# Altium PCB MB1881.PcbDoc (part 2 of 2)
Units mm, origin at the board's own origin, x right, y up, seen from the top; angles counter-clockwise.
Board outline 150 x 109 mm, 4 copper layers (Top Layer, Layer 1, Layer 2, Bottom Layer), stack 1.782 mm thick; 66 components, 175 nets, 880 pads, 302 vias.
Unrouted connection lines stored in the file: 35.
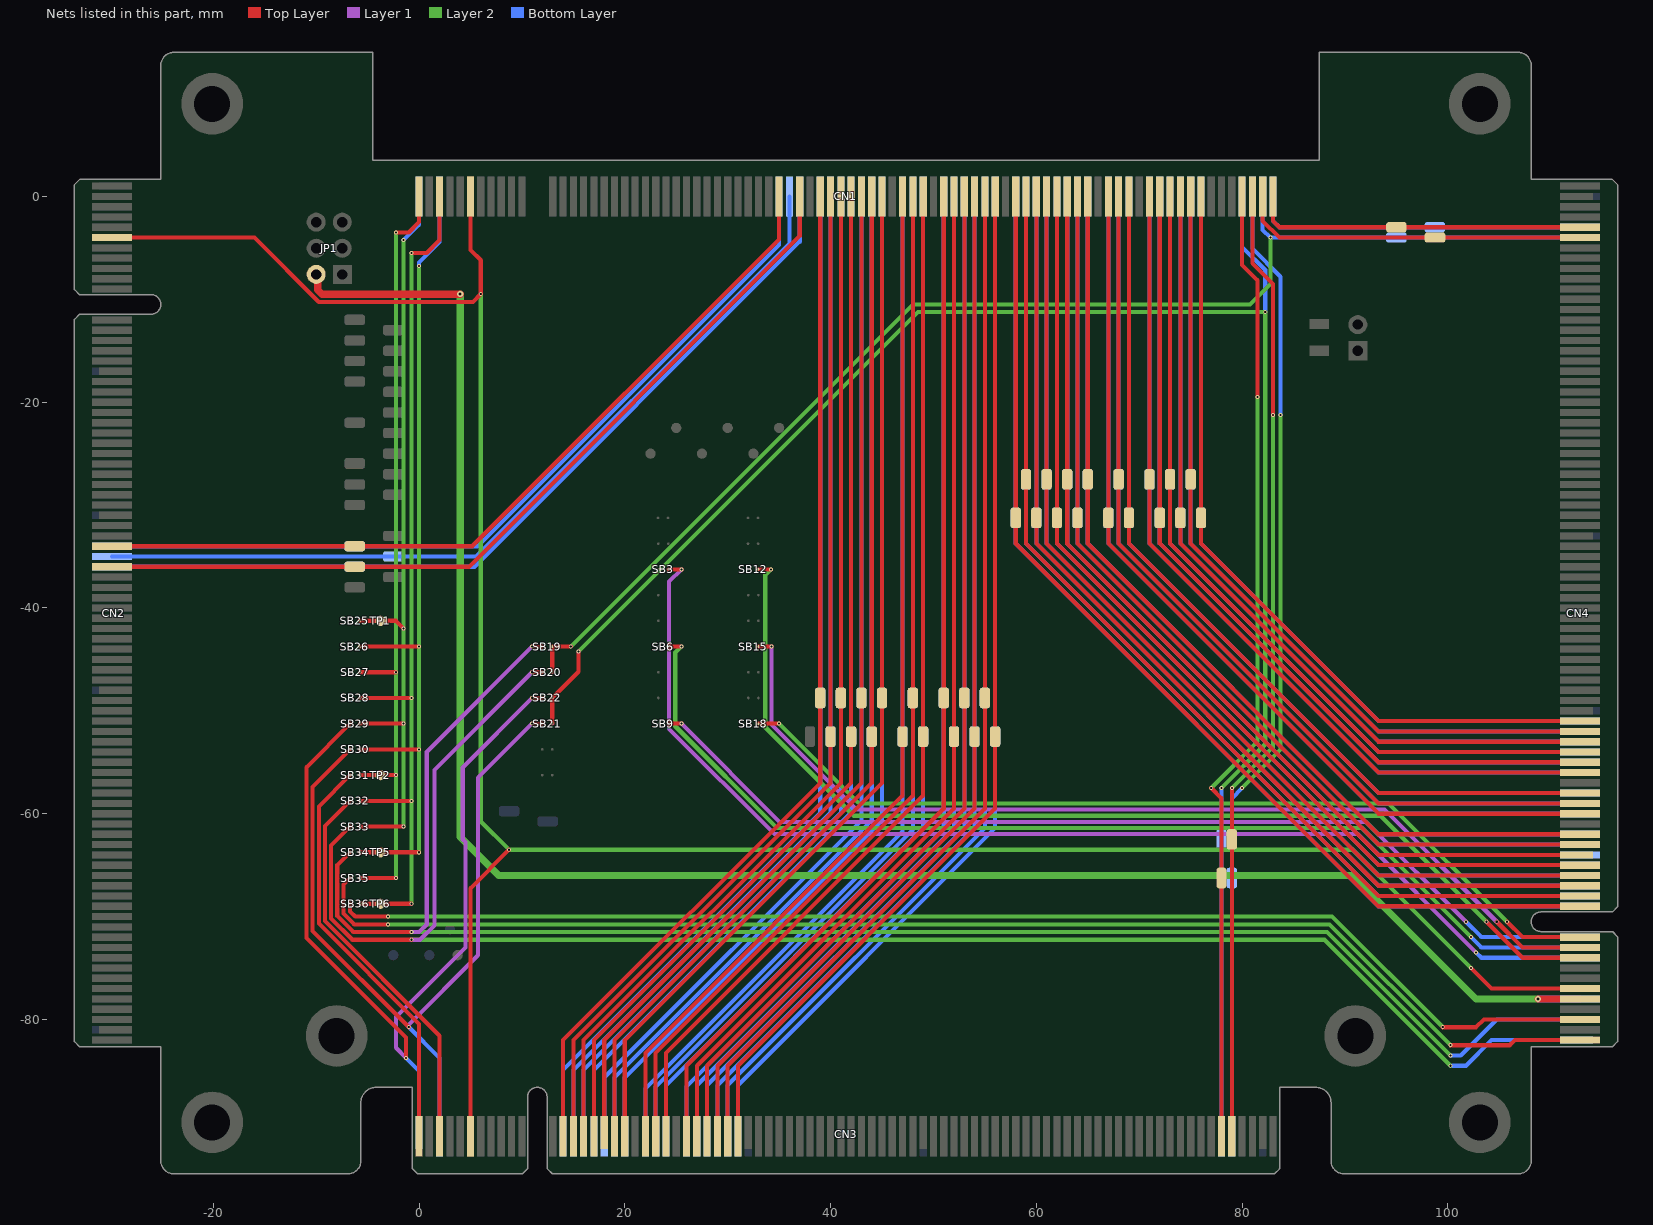
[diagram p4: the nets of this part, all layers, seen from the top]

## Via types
v1: diameter 0.6, hole 0.3, Top Layer to Bottom Layer, 181 vias
v2: diameter 0.381, hole 0.203, Top Layer to Bottom Layer, 121 vias

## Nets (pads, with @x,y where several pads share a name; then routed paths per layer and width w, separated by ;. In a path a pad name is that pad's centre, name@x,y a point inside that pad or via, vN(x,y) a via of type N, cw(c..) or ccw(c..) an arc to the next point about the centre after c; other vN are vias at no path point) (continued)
M2_D_BRAKE: CN1.A55 CN3.A30 pad.TP@56,-52.5 | length 101.7
  Bottom Layer w0.4: CN3.A30@31,-91.35 31,-86.395 56,-61.395 pad.TP@56,-52.5 CN1.A55@56,0
M2_Enable_A: CN1.A80 CN3.A78 pad.TP@79,-66.25 | length 94.5
  Layer 2 w0.4: v2(80,-57.5) 83.75,-53.75 v2(83.75,-21.25)
  Bottom Layer w0.4: CN3.A78@79,-91.35 79,-58.5 v2(80,-57.5) ; CN1.A80@81,0 81,-5.058 83.75,-7.808 v2(83.75,-21.25)
M2_Enable_B1: CN1.B79 CN3.B77 pad.TP@78,-66.25 | length 94.2
  Top Layer w0.4: v2(77,-57.5) 78,-58.5 CN3.B77@78,-91.35 ; CN1.B79@80,0 80,-6.654 81.5,-8.154 v2(81.5,-19.5)
  Layer 2 w0.4: v2(77,-57.5) 81.5,-53 v2(81.5,-19.5)
M2_Enable_B2: CN1.B80 CN3.B78 pad.TP@79,-62.5 | length 93.8
  Top Layer w0.4: CN3.B78@79,-91.35 v2(79,-57.5) ; CN1.B80@81,0 81,-6.5 83,-8.5 v2(83,-21.25)
  Layer 2 w0.4: v2(79,-57.5) 83,-53.5 v2(83,-21.25)
M2_Encoder_A: CN1.B41 CN3.B16 pad.TP@42,-52.5 | length 101.7
  Top Layer w0.4: CN3.B16@17,-91.35 17,-82 42,-57 CN1.B41@42,0
M2_Encoder_B: CN1.B42 CN3.B17 pad.TP@43,-48.75 | length 101.4
  Top Layer w0.4: CN3.B17@18,-90.995 18,-82 43,-57 CN1.B42@43,0
M2_Encoder_Z: CN1.B43 CN3.B18 pad.TP@44,-52.5 | length 101.7
  Top Layer w0.4: CN3.B18@19,-91.35 19,-82 44,-57 CN1.B43@44,0
M2_Hall_H1: CN1.A43 CN3.A18 pad.TP@44,-52.5 | length 101.7
  Bottom Layer w0.4: CN3.A18@19,-91.35 19,-85.65 44,-60.65 CN1.A43@44,0
M2_Hall_H2: CN1.A44 CN3.A19 pad.TP@45,-48.75 | length 101.7
  Bottom Layer w0.4: CN3.A19@20,-91.35 20,-85.65 45,-60.65 CN1.A44@45,0
M2_Hall_H3: CN1.B44 CN3.B19 pad.TP@45,-48.75 | length 101.7
  Top Layer w0.4: CN3.B19@20,-91.35 20,-82 45,-57 CN1.B44@45,0
M2_Master_EN: CN1.A41 CN3.A16 pad.TP@42,-52.5 | length 101.7
  Bottom Layer w0.4: CN3.A16@17,-91.35 17,-84.9 42,-59.9 CN1.A41@42,0
M2_PWM_UH: CN1.A38 CN3.A13 pad.TP@39,-48.75 | length 101.7
  Bottom Layer w0.4: CN3.A13@14,-91.35 14,-84.9 39,-59.9 CN1.A38@39,0
M2_PWM_UL: CN1.B38 CN3.B13 pad.TP@39,-48.75 | length 101.7
  Top Layer w0.4: CN3.B13@14,-91.35 14,-82 39,-57 CN1.B38@39,0
M2_PWM_VH: CN1.A39 CN3.A14 pad.TP@40,-52.5 | length 101.7
  Bottom Layer w0.4: CN3.A14@15,-91.35 15,-84.9 40,-59.9 CN1.A39@40,0
M2_PWM_VL: CN1.B39 CN3.B14 pad.TP@40,-52.5 | length 101.7
  Top Layer w0.4: CN3.B14@15,-91.35 15,-82 40,-57 CN1.B39@40,0
M2_PWM_WH: CN1.A40 CN3.A15 pad.TP@41,-48.75 | length 101.7
  Bottom Layer w0.4: CN3.A15@16,-91.35 16,-84.9 41,-59.9 CN1.A40@41,0
M2_PWM_WL: CN1.B40 CN3.B15 pad.TP@41,-48.75 | length 101.7
  Top Layer w0.4: CN3.B15@16,-91.35 16,-82 41,-57 CN1.B40@41,0
M2_Res.Ex: CN1.B53 CN3.B28 pad.TP@54,-52.5 | length 101.7
  Top Layer w0.4: CN3.B28@29,-91.35 29,-84.5 54,-59.5 CN1.B53@54,0
M2_Resolv_Cos: CN1.B55 CN3.B30 pad.TP@56,-52.5 | length 101.7
  Top Layer w0.4: CN3.B30@31,-91.35 31,-84.5 56,-59.5 CN1.B55@56,0
M2_Resolv_Sin: CN1.B54 CN3.B29 pad.TP@55,-48.75 | length 101.7
  Top Layer w0.4: CN3.B29@30,-91.35 30,-84.5 55,-59.5 CN1.B54@55,0
M2_SHUNT1+: CN1.A46 CN3.A21 pad.TP@47,-52.5 | length 101.7
  Bottom Layer w0.4: CN3.A21@22,-91.35 22,-86.708 47,-61.708 CN1.A46@47,0
M2_SHUNT1-: CN1.B46 CN3.B21 pad.TP@47,-52.5 | length 101.7
  Top Layer w0.4: CN3.B21@22,-91.35 22,-83.25 47,-58.25 CN1.B46@47,0
M2_SHUNT2+: CN1.A47 CN3.A22 pad.TP@48,-48.75 | length 101.7
  Bottom Layer w0.4: CN3.A22@23,-91.35 23,-86.554 48,-61.554 CN1.A47@48,0
M2_SHUNT2-: CN1.B47 CN3.B22 pad.TP@48,-48.75 | length 101.7
  Top Layer w0.4: CN3.B22@23,-91.35 23,-83.25 48,-58.25 CN1.B47@48,0
M2_SHUNT3+: CN1.A48 CN3.A23 pad.TP@49,-52.5 | length 101.7
  Bottom Layer w0.4: CN3.A23@24,-91.35 24,-86.4 49,-61.4 CN1.A48@49,0
M2_SHUNT3-: CN1.B48 CN3.B23 pad.TP@49,-52.5 | length 101.7
  Top Layer w0.4: CN3.B23@24,-91.35 24,-83.25 49,-58.25 CN1.B48@49,0
M2_SPI1_MISO: CN3.B01 SB31.2 | length 40.4
  Top Layer w0.4: SB31.2@-6.7,-56.25 -9.741,-59.291 -9.741,-70.687 0,-80.427 CN3.B01@0,-91.35
M2_SPI1_nSS: CN3.A01 SB22.2 SB29.2 | length 88.1
  Top Layer w0.4: SB29.2@-6.7,-51.25 -10.937,-55.487 -10.937,-72.063 -1.25,-81.75 v2(-1.25,-83.75) ; v2@11,-48.75 SB22.2@11.975,-48.75
  Layer 1 w0.4: v2(-1.25,-83.75) -2.25,-82.75 -2.25,-79.75 4.5,-73 4.5,-62.75 4.25,-62.5 4.25,-55.5 v2(11,-48.75)
  Bottom Layer w0.4: v2(-1.25,-83.75) 0,-85 CN3.A01@0,-90.995
M2_SPI2_MISO: CN3.B03 SB32.2 | length 38.2
  Top Layer w0.4: SB32.2@-6.7,-58.75 -9.142,-61.193 -9.142,-70.439 2,-81.582 CN3.B03@2,-91.35
M2_SPI2_nSS: CN3.A03 SB21.2 SB30.2 | length 79.4
  Top Layer w0.4: SB30.2@-6.7,-53.75 -10.339,-57.389 -10.339,-71.411 v2(-1,-80.75) ; v2@11,-51.25 SB21.2@11.975,-51.25
  Layer 1 w0.4: -0.991,-80.5 5.75,-73.759 5.75,-56.5 v2(11,-51.25)
  Bottom Layer w0.4: v2(-1,-80.75) 2,-83.75 CN3.A03@2,-91.35
M2_SPI_nSS: CN1.A79 CN3.A77 pad.TP@78,-62.5 SB21.1 SB22.1 | length 183.7
  Top Layer w0.4: SB21.1@12.95,-51.25 SB22.1@12.95,-48.75 15.5,-46.2 v2(15.5,-44.25)
  Layer 2 w0.4: v2(15.5,-44.25) 48.5,-11.25 v2(82.25,-11.25) 82.25,-53.25 v2(78,-57.5)
  Bottom Layer w0.18: CN3.A77@78,-92.5 CN3.A77@78,-91.35
  Bottom Layer w0.4: CN3.A77@78,-91.35 v2(78,-57.5) ; CN1.A79@80,0 80,-4.904 82.25,-7.154 v2(82.25,-11.25)
M2_TEMP_ID: CN1.A53 CN3.A28 pad.TP@54,-52.5 | length 101.7
  Bottom Layer w0.4: CN3.A28@29,-91.35 29,-86.395 54,-61.395 pad.TP@54,-52.5 CN1.A53@54,0
M2_Timer_ETR: CN1.A42 CN3.A17 pad.TP@43,-48.75 | length 101.7
  Bottom Layer w0.4: CN3.A17@18,-91.35 18,-85.65 43,-60.65 CN1.A42@43,0
M2_VBUS: CN1.A54 CN3.A29 pad.TP@55,-48.75 | length 101.7
  Bottom Layer w0.4: CN3.A29@30,-91.35 30,-86.395 55,-61.395 pad.TP@55,-48.75 CN1.A54@55,0
M2_VOL+_U: CN1.A50 CN3.A25 pad.TP@51,-48.75 | length 101.7
  Bottom Layer w0.4: CN3.A25@26,-91.35 26,-86.5 51,-61.5 pad.TP@51,-48.75 CN1.A50@51,0
M2_VOL+_V: CN1.A51 CN3.A26 pad.TP@52,-52.5 | length 101.7
  Bottom Layer w0.4: CN3.A26@27,-91.35 27,-86.395 52,-61.395 pad.TP@52,-52.5 CN1.A51@52,0
M2_VOL+_W: CN1.A52 CN3.A27 pad.TP@53,-48.75 | length 101.7
  Bottom Layer w0.4: CN3.A27@28,-91.35 28,-86.395 53,-61.395 pad.TP@53,-48.75 CN1.A52@53,0
M2_VOL-_U: CN1.B50 CN3.B25 pad.TP@51,-48.75 | length 101.7
  Top Layer w0.4: CN3.B25@26,-91.35 26,-84.5 51,-59.5 CN1.B50@51,0
M2_VOL-_V: CN1.B51 CN3.B26 pad.TP@52,-52.5 | length 101.7
  Top Layer w0.4: CN3.B26@27,-91.35 27,-84.5 52,-59.5 CN1.B51@52,0
M2_VOL-_W: CN1.B52 CN3.B27 pad.TP@53,-48.75 | length 101.7
  Top Layer w0.4: CN3.B27@28,-91.35 28,-84.5 53,-59.5 CN1.B52@53,0
M3_5V: CN4.A05 CN4.B05 JP1.2 | length 187.3
  Top Layer w0.7: JP1.2@-9.85,-8.08 -9.85,-9.09 -9.44,-9.5 v1(4,-9.5) ; v1(108.75,-78) CN4.B05@112.855,-78
  Layer 2 w0.7: v1(4,-9.5) 4,-62.27 7.74,-66.01 7.75,-66 90.73,-66 102.73,-78 v1(108.75,-78)
  Bottom Layer w0.7: v1(108.75,-78) CN4.A05@112.855,-78
M3_ADC_1: CN4.A09 SB3.1 | length 115
  Top Layer w0.4: SB3.1@24.238,-36.25 v2(25.5,-36.25)
  Layer 1 w0.4: v2(25.5,-36.25) 24.304,-37.446 24.304,-51.745 34.549,-61.991 91.241,-61.991 v2(102.75,-73.5)
  Bottom Layer w0.4: v2(102.75,-73.5) 103.25,-74 104,-74 CN4.A09@112.855,-74
M3_ADC_2: CN4.A10 SB6.1 | length 106.1
  Top Layer w0.4: SB6.1@24.238,-43.75 v2(25.5,-43.75)
  Layer 2 w0.4: v2(25.5,-43.75) 24.902,-44.348 24.902,-51.498 34.797,-61.392 91.642,-61.392 v2(102.25,-72)
  Bottom Layer w0.4: v2(102.25,-72) 103.25,-73 CN4.A10@112.855,-73
M3_ADC_3: CN4.A11 SB9.1 | length 97.2
  Top Layer w0.4: SB9.1@24.238,-51.25 v2(25.5,-51.25)
  Layer 1 w0.4: v2(25.5,-51.25) 35.044,-60.794 92.044,-60.794 v2(101.75,-70.5)
  Bottom Layer w0.4: v2(101.75,-70.5) 103.25,-72 CN4.A11@112.855,-72
M3_ADC_4: CN4.B09 SB12.1 | length 105.3
  Top Layer w0.4: SB12.1@32.95,-36.25 v2(34.213,-36.25) ; v2(103.75,-70.5) 107.25,-74 CN4.B09@112.855,-74
  Layer 2 w0.4: v2(34.213,-36.25) 33.652,-36.811 33.652,-51.594 42.255,-60.196 93.446,-60.196 v2(103.75,-70.5)
M3_ADC_5: CN4.B10 SB15.1 | length 96.4
  Top Layer w0.4: SB15.1@32.988,-43.75 v2@34.25,-43.75 ; v2(104.75,-70.5) 107.25,-73 CN4.B10@112.855,-73
  Layer 1 w0.4: v2(34.25,-43.75) 34.25,-51.346 42.502,-59.598 93.848,-59.598 v2(104.75,-70.5)
M3_ADC_6: CN4.B11 SB18.1 | length 88.5
  Top Layer w0.4: SB18.1@32.988,-51.25 v2(35,-51.25) ; v2(105.75,-70.5) 107.25,-72 CN4.B11@112.855,-72
  Layer 2 w0.4: v2(35,-51.25) 42.75,-59 94.25,-59 v2(105.75,-70.5)
M3_BKIN: CN1.A57 CN4.A12 pad.TP@58,-31.25 | length 103.2
  Bottom Layer w0.4: CN1.A57@58,0 pad.TP@58,-31.25 58,-33.75 93.25,-69 CN4.A12@112.855,-69
M3_BKIN2: CN1.B57 CN4.B12 pad.TP@58,-31.25 | length 103.5
  Top Layer w0.4: CN1.B57@58,0 pad.TP@58,-31.25 58,-33.75 93.25,-69 CN4.B12@113.1,-69
M3_D_BRAKE: CN1.A75 CN4.A30 pad.TP@76,-31.25 | length 77.8
  Bottom Layer w0.4: CN1.A75@76,0 pad.TP@76,-31.25 76,-33.75 93.25,-51 CN4.A30@112.855,-51
M3_Enable_A: CN1.A82 CN4.A78 pad.TP@98.74,-3 | length 33.5
  Bottom Layer w0.4: CN1.A82@83,0 83,-2.37 83.63,-3 CN4.A78@113.85,-3
M3_Enable_B1: CN1.B81 CN4.B77 pad.TP@98.75,-4 | length 33.9
  Top Layer w0.4: CN1.B81@82,0 82,-2.37 83.63,-4 CN4.B77@112.855,-4
M3_Enable_B2: CN1.B82 CN4.B78 pad.TP@95,-3 | length 32.5
  Top Layer w0.4: CN1.B82@83,0 83,-2.37 83.63,-3 CN4.B78@112.855,-3
M3_Encoder_A: CN1.B61 CN4.B16 pad.TP@62,-31.25 | length 97.8
  Top Layer w0.4: CN1.B61@62,0 pad.TP@62,-31.25 62,-33.75 93.25,-65 CN4.B16@113.1,-65
M3_Encoder_B: CN1.B62 CN4.B17 pad.TP@63,-27.5 | length 95.8
  Top Layer w0.4: CN1.B62@63,0 pad.TP@63,-27.5 63,-33.75 93.25,-64 CN4.B17@112.5,-64
M3_Encoder_Z: CN1.B63 CN4.B18 pad.TP@64,-31.25 | length 94.7
  Top Layer w0.4: CN1.B63@64,0 pad.TP@64,-31.25 64,-33.75 93.25,-63 CN4.B18@112.855,-63
M3_Hall_H1: CN1.A63 CN4.A18 pad.TP@64,-31.25 | length 94.7
  Bottom Layer w0.4: CN1.A63@64,0 64,-25 64,-33.75 93.25,-63 CN4.A18@112.855,-63
M3_Hall_H2: CN1.A64 CN4.A19 pad.TP@65,-27.5 | length 93.3
  Bottom Layer w0.4: CN1.A64@65,0 65,-25 65,-33.75 93.25,-62 CN4.A19@112.855,-62
M3_Hall_H3: CN1.B64 CN4.B19 pad.TP@65,-27.5 | length 93.3
  Top Layer w0.4: CN1.B64@65,0 pad.TP@65,-27.5 65,-33.75 93.25,-62 CN4.B19@112.855,-62
M3_Master_EN: CN1.A61 CN4.A16 pad.TP@62,-31.25 | length 97.5
  Bottom Layer w0.4: CN1.A61@62,0 62,-25 pad.TP@62,-31.25 62,-33.75 93.25,-65 CN4.A16@112.855,-65
M3_PWM_UH: CN1.A58 CN4.A13 pad.TP@59,-27.5 | length 101.8
  Bottom Layer w0.4: CN1.A58@59,0 59,-25 59,-28.75 59,-33.75 93.25,-68 CN4.A13@112.855,-68
M3_PWM_UL: CN1.B58 CN4.B13 pad.TP@59,-27.5 | length 102
  Top Layer w0.4: CN1.B58@59,0 pad.TP@59,-27.5 59,-33.75 93.25,-68 CN4.B13@113.1,-68
M3_PWM_VH: CN1.A59 CN4.A14 pad.TP@60,-31.25 | length 100.4
  Bottom Layer w0.4: CN1.A59@60,0 60,-25.25 pad.TP@60,-31.25 60,-33.75 93.25,-67 CN4.A14@112.855,-67
M3_PWM_VL: CN1.B59 CN4.B14 pad.TP@60,-31.25 | length 100.6
  Top Layer w0.4: CN1.B59@60,0 pad.TP@60,-31.25 60,-33.75 93.25,-67 CN4.B14@113.1,-67
M3_PWM_WH: CN1.A60 CN4.A15 pad.TP@61,-27.5 | length 99
  Bottom Layer w0.4: CN1.A60@61,0 61,-25.25 61,-28.75 61,-33.75 93.25,-66 CN4.A15@112.855,-66
M3_PWM_WL: CN1.B60 CN4.B15 pad.TP@61,-27.5 | length 99.2
  Top Layer w0.4: CN1.B60@61,0 pad.TP@61,-27.5 61,-33.75 93.25,-66 CN4.B15@113.1,-66
M3_Res.Ex: CN1.B73 CN4.B28 pad.TP@74,-31.25 | length 80.8
  Top Layer w0.4: CN1.B73@74,0 pad.TP@74,-31.25 74,-33.75 93.25,-53 CN4.B28@113.1,-53
M3_Resolv_Cos: CN1.B75 CN4.B30 pad.TP@76,-31.25 | length 78
  Top Layer w0.4: CN1.B75@76,0 pad.TP@76,-31.25 76,-33.75 93.25,-51 CN4.B30@113.1,-51
M3_Resolv_Sin: CN1.B74 CN4.B29 pad.TP@75,-27.5 | length 79.4
  Top Layer w0.4: CN1.B74@75,0 pad.TP@75,-27.5 75,-33.75 93.25,-52 CN4.B29@113.1,-52
M3_SHUNT1+: CN1.A66 CN4.A21 pad.TP@67,-31.25 | length 90.5
  Bottom Layer w0.4: CN1.A66@67,0 67,-25 67,-33.75 93.25,-60 CN4.A21@112.855,-60
M3_SHUNT1-: CN1.B66 CN4.B21 pad.TP@67,-31.25 | length 90.5
  Top Layer w0.4: CN1.B66@67,0 pad.TP@67,-31.25 67,-33.75 93.25,-60 CN4.B21@112.855,-60
M3_SHUNT2+: CN1.A67 CN4.A22 pad.TP@68,-27.5 | length 89.1
  Bottom Layer w0.4: CN1.A67@68,0 68,-25 68,-28.75 68,-33.75 93.25,-59 CN4.A22@112.855,-59
M3_SHUNT2-: CN1.B67 CN4.B22 pad.TP@68,-27.5 | length 89.3
  Top Layer w0.4: CN1.B67@68,0 pad.TP@68,-27.5 68,-33.75 93.25,-59 CN4.B22@113.1,-59
M3_SHUNT3+: CN1.A68 CN4.A23 pad.TP@69,-31.25 | length 87.6
  Bottom Layer w0.4: CN1.A68@69,0 69,-25 69,-33.75 93.25,-58 CN4.A23@112.855,-58
M3_SHUNT3-: CN1.B68 CN4.B23 pad.TP@69,-31.25 | length 87.9
  Top Layer w0.4: CN1.B68@69,0 pad.TP@69,-31.25 69,-33.75 93.25,-58 CN4.B23@113.1,-58
M3_SPI1_MISO: CN4.B01 SB35.2 | length 129.4
  Top Layer w0.4: SB35.2@-6.7,-66.25 -7.348,-66.898 -7.348,-69.696 -6.294,-70.75 v2(-3,-70.75) ; v2(100.25,-82.5) 106.014,-82.5 106.514,-82 CN4.B01@112.855,-82
  Layer 2 w0.4: v2(-3,-70.75) 88.5,-70.75 v2(100.25,-82.5)
M3_SPI1_nSS: CN4.A01 SB20.2 SB33.2 | length 170
  Top Layer w0.4: SB33.2@-6.7,-61.25 -8.544,-63.094 -8.544,-70.191 -6.486,-72.25 v2(-0.75,-72.25) ; v2@11,-46.25 SB20.2@11.975,-46.25
  Layer 1 w0.4: v2(-0.75,-72.25) 0.096,-72.25 1.5,-70.846 1.5,-55.75 v2(11,-46.25)
  Layer 2 w0.4: v2(-0.75,-72.25) 88,-72.25 v2(100.25,-84.5)
  Bottom Layer w0.4: v2(100.25,-84.5) 101.75,-84.5 104.25,-82 CN4.A01@112.5,-82
M3_SPI2_MISO: CN4.B03 SB36.2 | length 125.3
  Top Layer w0.4: SB36.2@-6.7,-68.75 -6.7,-69.498 -6.198,-70 v2(-3,-70) ; v2(99.5,-80.75) 102.75,-80.75 103.5,-80 CN4.B03@112.855,-80
  Layer 2 w0.4: v2(-3,-70) 88.75,-70 v2(99.5,-80.75)
M3_SPI2_nSS: CN4.A03 SB19.2 SB34.2 | length 168.6
  Top Layer w0.4: SB34.2@-6.7,-63.75 -7.946,-64.996 -7.946,-69.944 -6.39,-71.5 v2(-0.75,-71.5) ; v2@11,-43.75 SB19.2@11.975,-43.75
  Layer 1 w0.4: v2(-0.75,-71.5) 0,-71.5 0.75,-70.75 0.75,-54 v2(11,-43.75)
  Layer 2 w0.4: v2(-0.75,-71.5) 88.25,-71.5 v2(100.25,-83.5)
  Bottom Layer w0.4: v2(100.25,-83.5) 101.25,-83.5 104.75,-80 CN4.A03@112.855,-80
M3_SPI_nSS: CN1.A81 CN4.A77 pad.TP@95,-4 SB19.1 SB20.1 | length 126.8
  Top Layer w0.4: SB20.1@12.95,-46.25 SB19.1@12.95,-43.75 v2@14.75,-43.75
  Layer 2 w0.4: v2(14.75,-43.75) 48,-10.5 80.75,-10.5 82.75,-8.5 v2(82.75,-4)
  Bottom Layer w0.4: CN1.A81@82,0 82,-3.25 82.75,-4 CN4.A77@113.85,-4
M3_TEMP_ID: CN1.A73 CN4.A28 pad.TP@74,-31.25 | length 80.6
  Bottom Layer w0.4: CN1.A73@74,0 74,-25.25 74,-33.75 93.25,-53 CN4.A28@112.855,-53
M3_Timer_ETR: CN1.A62 CN4.A17 pad.TP@63,-27.5 | length 96.1
  Bottom Layer w0.4: CN1.A62@63,0 63,-25 63,-28.75 63,-33.75 93.25,-64 CN4.A17@112.855,-64
M3_VBUS: CN1.A74 CN4.A29 pad.TP@75,-27.5 | length 79.2
  Bottom Layer w0.4: CN1.A74@75,0 75,-33.75 93.25,-52 CN4.A29@112.855,-52
M3_VOL+_U: CN1.A70 CN4.A25 pad.TP@71,-27.5 | length 84.8
  Bottom Layer w0.4: CN1.A70@71,0 71,-24.75 71,-28.75 71,-33.75 93.25,-56 CN4.A25@112.855,-56
M3_VOL+_V: CN1.A71 CN4.A26 pad.TP@72,-31.25 | length 83.4
  Bottom Layer w0.4: CN1.A71@72,0 72,-24.75 pad.TP@72,-31.25 72,-33.75 93.25,-55 CN4.A26@112.855,-55
M3_VOL+_W: CN1.A72 CN4.A27 pad.TP@73,-27.5 | length 82
  Bottom Layer w0.4: CN1.A72@73,0 73,-25 73,-28.75 73,-33.75 93.25,-54 CN4.A27@112.855,-54
M3_VOL-_U: CN1.B70 CN4.B25 pad.TP@71,-27.5 | length 85.1
  Top Layer w0.4: CN1.B70@71,0 pad.TP@71,-27.5 71,-33.75 93.25,-56 CN4.B25@113.1,-56
M3_VOL-_V: CN1.B71 CN4.B26 pad.TP@72,-31.25 | length 83.7
  Top Layer w0.4: CN1.B71@72,0 pad.TP@72,-31.25 72,-33.75 93.25,-55 CN4.B26@113.1,-55
M3_VOL-_W: CN1.B72 CN4.B27 pad.TP@73,-27.5 | length 82.2
  Top Layer w0.4: CN1.B72@73,0 pad.TP@73,-27.5 73,-33.75 93.25,-54 CN4.B27@113.1,-54
PFC_BKIN_OC: CN1.A35 CN2.A35 pad.TP@-2.5,-35 | length 83
  Bottom Layer w0.4: CN2.A35@-29.855,-35 5.557,-35 36,-4.557 CN1.A35@36,0
PFC_Current_1: CN1.A34 CN2.A34 pad.TP@-6.25,-34 | length 81.7
  Bottom Layer w0.4: CN2.A34@-29.855,-34 5.711,-34 35,-4.711 CN1.A34@35,0
PFC_Current_2: CN1.B34 CN2.B34 pad.TP@-6.25,-34 | length 81.4
  Top Layer w0.4: CN2.B34@-29.855,-34 5.174,-34 35,-4.174 CN1.B34@35,0
PFC_PWM_1: CN1.A36 CN2.A36 pad.TP@-6.25,-36 | length 84.3
  Bottom Layer w0.4: CN2.A36@-29.855,-36 5.403,-36 37,-4.403 CN1.A36@37,0
PFC_PWM_2: CN1.B36 CN2.B36 pad.TP@-6.25,-36 | length 84
  Top Layer w0.4: CN2.B36@-29.855,-36 4.866,-36 37,-3.866 CN1.B36@37,0
SPI1_MISO: CN1.B01 SB27.1 SB31.1 SB35.1 TP2.1 | length 78.3
  Top Layer w0.4: SB35.1@-5.725,-66.25 v2(-2.25,-66.25) ; SB31.1@-5.725,-56.25 v2(-2.25,-56.25) ; SB27.1@-5.725,-46.25 v2(-2.25,-46.25) ; v2(-2.25,-3.5) -1,-3.5 0,-2.5 CN1.B01@0,0
  Layer 2 w0.4: v2(-2.25,-66.25) v2(-2.25,-46.25) v2(-2.25,-3.5)
SPI1_nSS: CN1.A01 SB25.1 SB29.1 SB33.1 TP1.1 | length 74.9
  Top Layer w0.4: SB25.1@-5.762,-41.25 -2.25,-41.25 v2(-1.5,-42) ; SB33.1@-5.725,-61.25 v2(-1.5,-61.25) ; SB29.1@-5.725,-51.25 v2(-1.5,-51.25)
  Layer 2 w0.4: v2(-1.5,-61.25) v2(-1.5,-42) v2(-1.5,-4.25)
  Bottom Layer w0.4: v2(-1.5,-4.25) 0,-2.75 CN1.A01@0,0
SPI2_MISO: CN1.B03 SB28.1 SB32.1 SB36.1 TP6.1 | length 85.7
  Top Layer w0.4: SB36.1@-5.725,-68.75 v2(-0.75,-68.75) ; SB32.1@-5.725,-58.75 v2@-0.75,-58.75 ; SB28.1@-5.725,-48.75 v2@-0.75,-48.75 ; v2(-0.75,-5.5) 0.75,-5.5 2,-4.25 CN1.B03@2,0
  Layer 2 w0.4: v2(-0.75,-68.75) v2(-0.75,-48.75) v2(-0.75,-5.5)
  other v2: -0.75,-58.75
SPI2_nSS: CN1.A03 SB26.1 SB30.1 SB34.1 TP5.1 | length 81.8
  Top Layer w0.4: SB26.1@-5.762,-43.75 v2(0,-43.75) ; SB34.1@-5.725,-63.75 v2(0,-63.75) ; SB30.1@-5.725,-53.75 v2@0,-53.75
  Layer 2 w0.4: v2(0,-63.75) v2(0,-6.75)
  Bottom Layer w0.4: v2(0,-6.75) 0,-6.418 2,-4.418 CN1.A03@2,0
  other v2: 0,-53.75
VREF+: CN1.B06 CN2.B06 CN3.B06 CN4.B06 | length 242.9
  Top Layer w0.4: CN2.B06@-29.855,-4 -15.998,-4 -9.75,-10.248 5.252,-10.248 v2(6,-9.5) 6,-6.2 5,-5.2 CN1.B06@5,0 ; CN3.B06@5,-91.35 5,-67.25 v2(8.75,-63.5) ; v2(102.25,-75) 104.25,-77 CN4.B06@112.855,-77
  Layer 2 w0.4: v2(6,-9.5) 6,-60.75 v2(8.75,-63.5) 90.75,-63.5 v2(102.25,-75)
pads on no net: CN2.A37 CN2.A38 CN2.A39 CN2.A40 CN2.A41 CN2.A42 CN2.A43 CN2.A44 CN2.A46 CN2.A47 CN2.A48 CN2.A50 CN2.A51 CN2.A52 CN2.A53 CN2.A54 CN2.A55 CN2.A57 CN2.A58 CN2.A59 CN2.A60 CN2.A61 CN2.A62 CN2.A63 CN2.A64 CN2.A66 CN2.A67 CN2.A68 CN2.A70 CN2.A71 CN2.A72 CN2.A73 CN2.A74 CN2.A75 CN2.A79 CN2.A80 CN2.A81 CN2.A82 CN2.B37 CN2.B38 CN2.B39 CN2.B40 CN2.B41 CN2.B42 CN2.B43 CN2.B44 CN2.B46 CN2.B47 CN2.B48 CN2.B50 CN2.B51 CN2.B52 CN2.B53 CN2.B54 CN2.B55 CN2.B57 CN2.B58 CN2.B59 CN2.B60 CN2.B61 CN2.B62 CN2.B63 CN2.B64 CN2.B66 CN2.B67 CN2.B68 CN2.B70 CN2.B71 CN2.B72 CN2.B73 CN2.B74 CN2.B75 CN2.B79 CN2.B80 CN2.B81 CN2.B82 CN3.A33 CN3.A34 CN3.A35 CN3.A36 CN3.A37 CN3.A38 CN3.A39 CN3.A40 CN3.A41 CN3.A42 CN3.A43 CN3.A44 CN3.A46 CN3.A47 CN3.A48 CN3.A50 CN3.A51 CN3.A52 CN3.A53 CN3.A54 CN3.A55 CN3.A57 CN3.A58 CN3.A59 CN3.A60 CN3.A61 CN3.A62 CN3.A63 CN3.A64 CN3.A66 CN3.A67 CN3.A68 CN3.A70 CN3.A71 CN3.A72 CN3.A73 CN3.A74 CN3.A75 CN3.A79 CN3.A80 CN3.A81 CN3.A82 CN3.B33 CN3.B34 CN3.B35 CN3.B36 CN3.B37 CN3.B38 CN3.B39 CN3.B40 CN3.B41 CN3.B42 CN3.B43 CN3.B44 CN3.B46 CN3.B47 CN3.B48 CN3.B50 CN3.B51 CN3.B52 CN3.B53 CN3.B54 CN3.B55 CN3.B57 CN3.B58 CN3.B59 CN3.B60 CN3.B61 CN3.B62 CN3.B63 CN3.B64 CN3.B66 CN3.B67 CN3.B68 CN3.B70 CN3.B71 CN3.B72 CN3.B73 CN3.B74 CN3.B75 CN3.B79 CN3.B80 CN3.B81 CN3.B82 CN4.A33 CN4.A34 CN4.A35 CN4.A36 CN4.A37 CN4.A38 CN4.A39 CN4.A40 CN4.A41 CN4.A42 CN4.A43 CN4.A44 CN4.A46 CN4.A47 CN4.A48 CN4.A50 CN4.A51 CN4.A52 CN4.A53 CN4.A54 CN4.A55 CN4.A57 CN4.A58 CN4.A59 CN4.A60 CN4.A61 CN4.A62 CN4.A63 CN4.A64 CN4.A66 CN4.A67 CN4.A68 CN4.A70 CN4.A71 CN4.A72 CN4.A73 CN4.A74 CN4.A75 CN4.A79 CN4.A80 CN4.A81 CN4.A82 CN4.B33 CN4.B34 CN4.B35 CN4.B36 CN4.B37 CN4.B38 CN4.B39 CN4.B40 CN4.B41 CN4.B42 CN4.B43 CN4.B44 CN4.B46 CN4.B47 CN4.B48 CN4.B50 CN4.B51 CN4.B52 CN4.B53 CN4.B54 CN4.B55 CN4.B57 CN4.B58 CN4.B59 CN4.B60 CN4.B61 CN4.B62 CN4.B63 CN4.B64 CN4.B66 CN4.B67 CN4.B68 CN4.B70 CN4.B71 CN4.B72 CN4.B73 CN4.B74 CN4.B75 CN4.B79 CN4.B80 CN4.B81 CN4.B82 H1.1 H2.1 H3.1 H4.1 H5.1 H6.1

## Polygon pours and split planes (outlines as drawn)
DGND on Layer 1 "DGND_L02_P001" (solid, remove dead copper, pour order 1): -4.753,3.25 -4.753,13.747 -24.247,13.747 -24.25,13.75 -25,13 -25,1.5 -33,1.5 -33.25,1.25 -33.25,-9 -33,-9.25 -25.5,-9.25 -24.75,-10 -24.75,-11 -25.5,-11.75 -33,-11.75 -33.25,-12 -33.25,-82.25 -33,-82.5 -25,-82.5 -25,-94 -24.25,-94.75 -6.5,-94.75 -5.75,-94 -5.75,-87.5 -4.5,-86.25 -0.75,-86.25 -0.5,-86.5 -0.5,-94.495 -0.245,-94.75 9.995,-94.75 10.25,-94.495 10.25,-87 11,-86.25 12,-86.25 12.75,-87 12.75,-94.495 13.005,-94.75 83.245,-94.75 83.5,-94.495 83.5,-86.5 83.75,-86.25 87.75,-86.25 88.75,-87.25 88.75,-94 89.5,-94.75 107.25,-94.75 108,-94 108,-82.5 116,-82.5 116.25,-82.25 116.25,-71.95 116,-71.75 108.5,-71.75 107.75,-71 107.75,-70 108.5,-69.25 116,-69.25 116.25,-69 116.25,1.25 116,1.5 108,1.5 107.997,1.503 107.997,13.003 107.25,13.75 87.75,13.75 87.75,3.25
AGND on Top Layer "AGND_L01_P000" (solid, remove dead copper, pour order 0): 87.75,3.5 87.75,13.75 107.25,13.75 108,13 107.997,12.997 108,1.5 110.75,1.5 111,1.25 111,-69 110.75,-69.25 108.5,-69.25 107.75,-70 107.75,-71 108.5,-71.75 110.75,-71.75 111,-72 111,-82.25 110.75,-82.5 108,-82.5 108,-94 107.25,-94.75 89.75,-94.75 88.75,-93.75 88.75,-87.25 88,-86.5 83.5,-86.5 83.5,-89.25 83.25,-89.5 13,-89.5 12.75,-89.25 12.75,-87 12,-86.25 11,-86.25 10.25,-87 10.25,-89.25 10,-89.5 -0.25,-89.5 -0.5,-89.25 -0.5,-86.5 -4.75,-86.5 -5.75,-87.5 -5.75,-94 -6.5,-94.75 -24.25,-94.75 -25,-94 -25,-82.517 -24.991,-82.509 -25,-82.5 -27.75,-82.5 -28,-82.25 -28,-12 -27.75,-11.75 -25.5,-11.75 -24.75,-11 -24.75,-10 -25.5,-9.25 -27.75,-9.25 -28,-9 -28,1.25 -27.75,1.5 -25,1.5 -25,13 -24.25,13.75 -4.75,13.75 -4.753,13.747 -4.75,3.25 -0.5,3.25 -0.5,-2 83.5,-2 83.5,3.25 87.5,3.25
AGND on Layer 2 "AGND_L03_P004" (solid, remove dead copper, pour order 4): -4.75,3.25 -4.75,13.747 -24.243,13.747 -24.247,13.75 -24.997,13 -24.997,1.5 -32.997,1.5 -33.247,1.25 -33.247,-9 -32.997,-9.25 -25.497,-9.25 -24.747,-10 -24.747,-11 -25.497,-11.75 -32.997,-11.75 -33.247,-12 -33.247,-82.25 -32.997,-82.5 -24.997,-82.5 -24.997,-94 -24.247,-94.75 -6.497,-94.75 -5.747,-94 -5.747,-87.5 -4.497,-86.25 -0.747,-86.25 -0.497,-86.5 -0.497,-94.495 -0.242,-94.75 9.998,-94.75 10.253,-94.495 10.253,-87 11.003,-86.25 12.003,-86.25 12.753,-87 12.753,-94.495 13.008,-94.75 83.248,-94.75 83.503,-94.495 83.503,-86.5 83.753,-86.25 87.753,-86.25 88.753,-87.25 88.753,-94 89.503,-94.75 107.253,-94.75 108.003,-94 108.003,-82.5 116.003,-82.5 116.253,-82.25 116.253,-71.95 116.003,-71.75 108.503,-71.75 107.753,-71 107.753,-70 108.503,-69.25 116.003,-69.25 116.253,-69 116.253,1.25 116.003,1.5 108.003,1.5 108,1.503 108,13.003 107.253,13.75 87.753,13.75 87.753,3.25
DGND on Bottom Layer "DGND_L04_P003" (solid, remove dead copper, pour order 3): -25,1.48 -25,13 -24.993,13 -24.247,13.747 -4.753,13.747 -4.753,3.503 -4.718,3.25 -0.503,3.25 -0.503,-2.02 83.497,-2.02 83.497,3.25 87.753,3.25 87.753,13.75 107.253,13.75 107.997,13.007 107.997,1.48 110.747,1.48 110.997,1.23 110.997,-69.02 110.747,-69.27 108.497,-69.27 107.747,-70.02 107.747,-71.02 108.497,-71.77 110.747,-71.77 110.997,-72.02 110.997,-82.27 110.747,-82.52 107.997,-82.52 108,-82.524 108,-94 107.25,-94.75 89.5,-94.75 88.75,-94 88.75,-87.25 88.73,-87.25 88,-86.52 83.497,-86.52 83.497,-89.27 83.247,-89.52 12.997,-89.52 12.747,-89.27 12.747,-87.02 11.997,-86.27 10.997,-86.27 10.247,-87.02 10.247,-89.27 9.997,-89.52 -0.253,-89.52 -0.503,-89.27 -0.503,-86.52 -4.754,-86.52 -5.747,-87.497 -5.747,-94 -6.497,-94.75 -24.25,-94.75 -25,-94 -25,-82.524 -25.003,-82.52 -27.753,-82.52 -28.003,-82.27 -28.003,-12.02 -27.753,-11.77 -25.503,-11.77 -24.753,-11.02 -24.753,-10.02 -25.503,-9.27 -27.753,-9.27 -28.003,-9.02 -28.003,1.23 -27.753,1.48

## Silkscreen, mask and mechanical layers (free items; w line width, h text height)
Top Overlay:
  drawing of 488 lines, arcs and shapes, not listed
  text "M3" at 105,-0.25 h1.52
  text "M3_Enable_B2" at 92.5,-1.681 h1.8
  text "M1" at -14.75,-3.25 h1.52
  text "M2" at -14.775,-5.76 h1.52
  text "5V" at -5.4,-5.75 h1.52
  text "M3_Enable_B1" at 92.5,-6.181 h1.8
  text "M3" at -14.75,-8.25 h1.52
  text "M1" at -4,-11 h1.52
  text "BKIN2" at -13.313,-12.5 h1.8
  text "AGND" at 93.85,-13.27 h1.52
  text "PWM_UL" at 0,-13.431 h1.8
  text "PWM_VL" at -15.484,-14.431 h1.8
  text "PWM_WL" at 0,-15.431 h1.8
  text "DGND" at 93.85,-15.77 h1.52
  text "Encod_A" at -15.276,-16.431 h1.8
  text "Encod_B" at 0,-17.431 h1.8
  text "Encod_Z" at -15.144,-18.431 h1.8
  text "Hall_H3" at 0,-19.431 h1.8
  text "Shunt1-" at 0,-21.731 h1.8
  text "Shunt2-" at -14.383,-22.731 h1.8
  text "Shunt3-" at 0,-23.731 h1.8
  text "PWM_UL" at 59.431,-25 h1.8 r90
  text "PWM_WL" at 61.431,-25 h1.8 r90
  text "Encod_B" at 63.431,-25 h1.8 r90
  text "Hall_H3" at 65.431,-25 h1.8 r90
  text "Shunt2-" at 68.481,-25 h1.8 r90
  text "VOL-_U" at 71.431,-24.999 h1.8 r90
  text "VOL-_W" at 73.431,-24.999 h1.8 r90
  text "Resolv_Sin" at 75.431,-25 h1.8 r90
  text "VOL-_U" at 0.001,-25.431 h1.8
  text "F" at 87.5,-26.25 h14.99
  text "E" at 98.75,-26.25 h15
  text "VOL-_V" at -14.571,-26.431 h1.8
  text "VOL-_W" at 0.001,-27.431 h1.8
  text "Res_Ex" at -14.363,-28.431 h1.8
  text "ADC Selection" at 14.75,-29.231 h1.8
  text "Resolv_Sin" at 0,-29.431 h1.8
  text "Resolv_Cos" at -17.36,-30.431 h1.8
  text "M3" at 56.25,-30.5 h1.52 r90
  text "AC_Zero_Cross" at -0.001,-33.431 h1.8
  text "C" at 100,-33.75 h10
  text "PFC_Cur_2" at -17.157,-34.431 h1.8
  text "Inrush_Lim" at 0,-35.431 h1.8
  text "H" at 85,-36.25 h20
  text "PFC_PWM_2" at -18.5,-36.431 h1.8
  text "Enable_B1" at 0,-37.181 h1.8
  text "BKIN2" at 58.5,-38.25 h1.8 r90
  text "Enable_B2" at -16.534,-38.431 h1.8
  text "Res_Ex" at 74.431,-39.3 h1.8 r90
  text "Shunt1-" at 67.481,-39.32 h1.8 r90
  text "Shunt3-" at 69.481,-39.32 h1.8 r90
  text "VOL-_V" at 72.431,-39.508 h1.8 r90
  text "Encod_Z" at 64.431,-40.081 h1.8 r90
  text "Encod_A" at 62.431,-40.213 h1.8 r90
  text "PWM_VL" at 60.431,-40.421 h1.8 r90
  text "SPI Selection" at 2.5,-41.731 h1.8
  text "Resolv_Cos" at 76.431,-42.297 h1.8 r90
  text "G" at 86.25,-43.75 h15
  text "S" at 100,-43.75 h10
  text "PWM_UL" at 39.431,-46.25 h1.8 r90
  text "PWM_WL" at 41.431,-46.25 h1.8 r90
  text "Encod_B" at 43.431,-46.25 h1.8 r90
  text "Hall_H3" at 45.431,-46.25 h1.8 r90
  text "Shunt2-" at 48.481,-46.25 h1.8 r90
  text "VOL-_U" at 51.431,-46.248 h1.8 r90
  text "VOL-_W" at 53.431,-46.248 h1.8 r90
  text "Resolv_Sin" at 55.431,-46.25 h1.8 r90
  text "M2" at 36.5,-51.75 h1.52 r90
  text "BKIN2" at 38.5,-59.43 h1.8 r90
  text "Res_Ex" at 54.431,-60.48 h1.8 r90
  text "Shunt1-" at 47.481,-60.5 h1.8 r90
  text "Shunt3-" at 49.481,-60.5 h1.8 r90
  text "VOL-_V" at 52.431,-60.688 h1.8 r90
  text "Encod_Z" at 44.431,-61.261 h1.8 r90
  text "Encod_A" at 42.431,-61.393 h1.8 r90
  text "PWM_VL" at 40.431,-61.601 h1.8 r90
  text "Resolv_Cos" at 56.431,-63.478 h1.8 r90
  text "M2_Enable_B1" at 76.681,-67.5 h1.8 r90
  text "M2_Enable_B2" at 81.431,-67.5 h1.8 r90
  text "MB1881B" at 49.75,-70 h4
  text "M1" at -23.625,-81.51 h1.52
  text "I" at 67.5,-82.5 h20
  text "M2" at 83.475,-84.76 h1.52
  text "J" at 40,-87.5 h40
Bottom Overlay:
  drawing of 488 lines, arcs and shapes, not listed
  text "M3" at 106.75,-0.25 h1.52
  text "M3_Enable_A" at 101.25,-1.681 h1.8
  text "M3_SPI_nSS" at 101.25,-6.181 h1.8
  text "M1" at -3,-10 h1.52
  text "BKIN" at -8.75,-12.5 h1.8
  text "PWM_UH" at 6.903,-13.431 h1.8
  text "PWM_VH" at -8.75,-14.431 h1.8
  text "PWM_WH" at 7.261,-15.431 h1.8
  text "Master_EN" at -8.75,-16.431 h1.8
  text "Timer_ETR" at 63.431,-16.841 h1.8 r90
  text "Timer_ETR" at 8.172,-17.431 h1.8
  text "PWM_WH" at 61.431,-17.752 h1.8 r90
  text "PWM_UH" at 59.431,-18.11 h1.8 r90
  text "Hall_H1" at -8.75,-18.431 h1.8
  text "VOL+_W" at 73.451,-18.487 h1.8 r90
  text "VOL+_U" at 71.451,-18.957 h1.8 r90
  text "Shunt2+" at 68.481,-19.25 h1.8 r90
  text "Hall_H2" at 5.513,-19.431 h1.8
  text "Hall_H2" at 65.431,-19.5 h1.8 r90
  text "VBUS" at 75.751,-20.75 h1.8 r90
  text "Shunt1+" at 6,-21.481 h1.8
  text "Shunt2+" at -8.75,-22.481 h1.8
  text "Shunt3+" at 6,-23.481 h1.8
  text "VOL+_U" at 6.085,-25.431 h1.8
  text "VOL+_V" at -8.751,-26.431 h1.8
  text "VOL+_W" at 6.555,-27.431 h1.8
  text "M3" at 56.25,-28 h1.52 r90
  text "TEMP_ID" at -8.75,-28.431 h1.8
  text "VBUS" at 4.249,-29.481 h1.8
  text "D_BRAKE" at -8.75,-30.431 h1.8
  text "AC_Voltage" at 8.534,-33.413 h1.8
  text "BKIN" at 58.75,-33.75 h1.8 r90
  text "PWM_VH" at 60.431,-33.75 h1.8 r90
  text "Master_EN" at 62.431,-33.75 h1.8 r90
  text "Hall_H1" at 64.431,-33.75 h1.8 r90
  text "Shunt1+" at 67.501,-33.75 h1.8 r90
  text "Shunt3+" at 69.501,-33.75 h1.8 r90
  text "TEMP_ID" at 74.431,-33.75 h1.8 r90
  text "D_BRAKE" at 76.431,-33.75 h1.8 r90
  text "VOL+_V" at 72.431,-33.752 h1.8 r90
  text "PFC_Curr_1" at -8.75,-34.431 h1.8
  text "PFC_BKIN_OC" at 11,-35.431 h1.8
  text "PFC_PWM_1" at -8.75,-36.431 h1.8
  text "Timer_ETR" at 43.431,-38.091 h1.8 r90
  text "PWM_WH" at 41.431,-39.002 h1.8 r90
  text "PWM_UH" at 39.431,-39.36 h1.8 r90
  text "VOL+_W" at 53.451,-39.737 h1.8 r90
  text "VOL+_U" at 51.451,-40.207 h1.8 r90
  text "Shunt2+" at 48.481,-40.5 h1.8 r90
  text "Hall_H2" at 45.431,-40.75 h1.8 r90
  text "VBUS" at 55.751,-42 h1.8 r90
  text "M2" at 36.25,-49.25 h1.52 r90
  text "BKIN" at 38.5,-55 h1.8 r90
  text "PWM_VH" at 40.431,-55 h1.8 r90
  text "Master_EN" at 42.431,-55 h1.8 r90
  text "Hall_H1" at 44.431,-55 h1.8 r90
  text "Shunt1+" at 47.501,-55 h1.8 r90
  text "Shunt3+" at 49.501,-55 h1.8 r90
  text "VOL+_V" at 52.431,-55.001 h1.8 r90
  text "TEMP_ID" at 54.431,-55 h1.8 r90
  text "D_BRAKE" at 56.431,-55 h1.8 r90
  text "M1_SPI_nSS" at 15.25,-58.431 h1.8
  text "M2_SPI_nSS" at 76.431,-60 h1.8 r90
  text "M2_Enable_A" at 81.181,-60 h1.8 r90
  text "M1_Enable_A" at 15.25,-62.931 h1.8
  text "M1" at -21.125,-81.51 h1.52
  text "M2" at 85.975,-84.76 h1.52
M1-Board Shape:
  lines w0.18: -25.105,1.655 -25.1,1.65 ; -25.1,-82.65 -25.1,-93.745 ccw(c-23.85,-93.745) -23.85,-94.995 -6.9,-94.995 ccw(c-6.9,-93.745) -5.65,-93.745 -5.65,-88.095 cw(c-4.15,-88.095) -4.15,-86.595 -0.65,-86.595 ; -25.1,1.655 -25.1,12.75 cw(c-23.85,12.75) -23.85,14 -4.5,14 -4.5,3.5 29.5,3.5 53.5,3.5 87.5,3.5 87.5,14 106.85,14 cw(c106.85,12.75) 108.1,12.75 108.1,1.65 ; 83.65,-86.595 87.145,-86.595 cw(c87.145,-88.095) 88.645,-88.095 88.645,-93.745 ccw(c89.895,-93.745) 89.895,-94.995 106.85,-94.995 ccw(c106.85,-93.745) 108.1,-93.745 108.1,-82.65
Drill Drawing:
  drawing of 464 lines, arcs and shapes, not listed
  text "Symbol" at -41.888,108.664 h1.54
  text "Count" at -30.958,108.664 h1.54
  text "Hole Size" at -18.284,108.664 h1.54
  text "Plated" at 5.489,108.664 h1.54
  text "Hole Type" at 16.419,108.664 h1.54
  text "Drill Layer Pair" at 32.215,108.664 h1.54
  text "Via/Pad" at 64.312,108.664 h1.54
  text "Pad Shape" at 77.034,108.664 h1.54
  text "Template" at 93.087,108.664 h1.54
  text "Description" at 110.457,108.664 h1.54
  text "Hole Tolerance (+)" at 128.814,108.664 h1.54
  text "Hole Tolerance (-)" at 157.416,108.664 h1.54
  text "121" at -30.958,105.461 h1.28
  text "8,00mil (0,20mm)" at -18.284,105.461 h1.28
  text "PTH" at 5.489,105.461 h1.28
  text "Round" at 16.419,105.461 h1.28
  text "Top Layer - Bottom Layer" at 32.215,105.461 h1.28
  text "Via" at 64.312,105.461 h1.28
  text "Rounded" at 77.034,105.461 h1.28
  text "v38h20" at 93.087,105.461 h1.28
  text "181" at -30.958,102.259 h1.28
  text "11,81mil (0,30mm)" at -18.284,102.259 h1.28
  text "PTH" at 5.489,102.259 h1.28
  text "Round" at 16.419,102.259 h1.28
  text "Top Layer - Bottom Layer" at 32.215,102.259 h1.28
  text "Via" at 64.312,102.259 h1.28
  text "Rounded" at 77.034,102.259 h1.28
  text "v60h30" at 93.087,102.259 h1.28
  text "8" at -30.958,99.056 h1.28
  text "39,37mil (1,00mm)" at -18.284,99.056 h1.28
  text "PTH" at 5.489,99.056 h1.28
  text "Round" at 16.419,99.056 h1.28
  text "Top Layer - Bottom Layer" at 32.215,99.056 h1.28
  text "Pad" at 64.312,99.056 h1.28
  text "Rounded" at 77.034,99.056 h1.28
  text "(Mixed)" at 93.087,99.056 h1.28
  text "6" at -30.958,95.854 h1.28
  text "137,79mil (3,50mm)" at -18.284,95.854 h1.28
  text "PTH" at 5.489,95.854 h1.28
  text "Round" at 16.419,95.854 h1.28
  text "Top Layer - Bottom Layer" at 32.215,95.854 h1.28
  text "Pad" at 64.312,95.854 h1.28
  text "Rounded" at 77.034,95.854 h1.28
  text "c600h350m605" at 93.087,95.854 h1.28
  text "316 Total" at -30.958,92.651 h1.28
  text "Layer" at 72.407,83.598 h1.52
  text "Name" at 82.819,83.598 h1.52
  text "Material" at 106.434,83.598 h1.52
  text "Thickness" at 128.272,83.598 h1.52
  text "Constant" at 144.778,83.598 h1.52
  text "Board Layer Stack" at 159.252,83.598 h1.52
  text "Top Overlay" at 82.819,80.55 h1.52
  text "Top Solder" at 82.819,77.502 h1.52
  text "Solder Resist" at 106.434,77.502 h1.52
  text "0,59mil" at 128.272,77.502 h1.52
  text "3,5" at 144.778,77.502 h1.52
  text "1" at 72.407,74.454 h1.52
  text "Top Layer" at 82.819,74.454 h1.52
  text "Copper" at 106.434,74.454 h1.52
  text "1,38mil" at 128.272,74.454 h1.52
  text "Dielectric 2" at 82.819,71.406 h1.52
  text "PP-006" at 106.434,71.406 h1.52
  text "2,80mil" at 128.272,71.406 h1.52
  text "4,1" at 144.778,71.406 h1.52
  text "2" at 72.407,68.358 h1.52
  text "Layer 1" at 82.819,68.358 h1.52
  text "Copper" at 106.434,68.358 h1.52
  text "1,38mil" at 128.272,68.358 h1.52
  text "Dielectric 1" at 82.819,65.31 h1.52
  text "FR-4" at 106.434,65.31 h1.52
  text "59,06mil" at 128.272,65.31 h1.52
  text "4,8" at 144.778,65.31 h1.52
  text "3" at 72.407,62.262 h1.52
  text "Layer 2" at 82.819,62.262 h1.52
  text "Copper" at 106.434,62.262 h1.52
  text "1,38mil" at 128.272,62.262 h1.52
  text "Dielectric 3" at 82.819,59.214 h1.52
  text "PP-006" at 106.434,59.214 h1.52
  text "2,80mil" at 128.272,59.214 h1.52
  text "4,1" at 144.778,59.214 h1.52
  text "4" at 72.407,56.166 h1.52
  text "Bottom Layer" at 82.819,56.166 h1.52
  text "Copper" at 106.434,56.166 h1.52
  text "1,38mil" at 128.272,56.166 h1.52
  text "Bottom Solder" at 82.819,53.118 h1.52
  text "Solder Resist" at 106.434,53.118 h1.52
  text "0,59mil" at 128.272,53.118 h1.52
  text "3,5" at 144.778,53.118 h1.52
  text "Bottom Overlay" at 82.819,50.07 h1.52
  text "20" at 163.495,29.303 h1.27
  text "20" at 163.495,29.303 h1.27
  text "1.57MM" at 176.157,10.634 h1.27
  text "1.57MM" at 176.157,10.634 h1.27
  text "0.062" at 175.637,7.586 h1.27
  text "1.30MM" at 156.256,7.42 h1.27 r90
  text "1.30MM" at 156.256,7.42 h1.27 r90
  text "0.051" at 159.304,6.9 h1.27 r90
  text "0.051" at 159.304,6.9 h1.27 r90
  text "B" at 111.825,3.99 h1.52
  text "DETAIL B" at 160.32,-2.447 h2.16
  text "DETAIL B" at 160.32,-2.447 h2.16

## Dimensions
88.645,-94.995 to 83.65,-94.495 on M2-Board Dimensions
-5.65,-94.995 to -0.65,-94.495 on M2-Board Dimensions
-25.1,-94.995 to -20.1,-90 on M2-Board Dimensions
-8,-81.595 to 91,-81.595 on M2-Board Dimensions
116.5,1.15 to 108.1,14 on M2-Board Dimensions
87.5,14 to 108.1,14 on M2-Board Dimensions
-33.5,1.15 to -25.1,14 on M2-Board Dimensions
-20.1,9 to -25.1,14 on M2-Board Dimensions
-20.1,9 to -25.1,14 on M2-Board Dimensions
-25.1,14 to -4.5,14 on M2-Board Dimensions
-0.15,-94.995 to -25.1,14 on M2-Board Dimensions
91,-81.595 to 103.1,-90 on M2-Board Dimensions
103.1,-90 to 108.1,-94.995 on M2-Board Dimensions
-20.1,9 to -33,1.65 on M2-Board Dimensions
-33,-82.65 to -20.1,-90 on M2-Board Dimensions
-20.1,-90 to -8,-81.595 on M2-Board Dimensions
-33.5,1.15 to 116.5,1.15 on M2-Board Dimensions
-25.1,14 to 108.1,14 on M2-Board Dimensions
91,-81.595 to 83.65,-94.495 on M2-Board Dimensions
-8,-81.595 to -0.65,-86.595 on M2-Board Dimensions
-8,-81.595 to -0.65,-94.495 on M2-Board Dimensions
103.1,9 to -20.1,9 on M2-Board Dimensions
